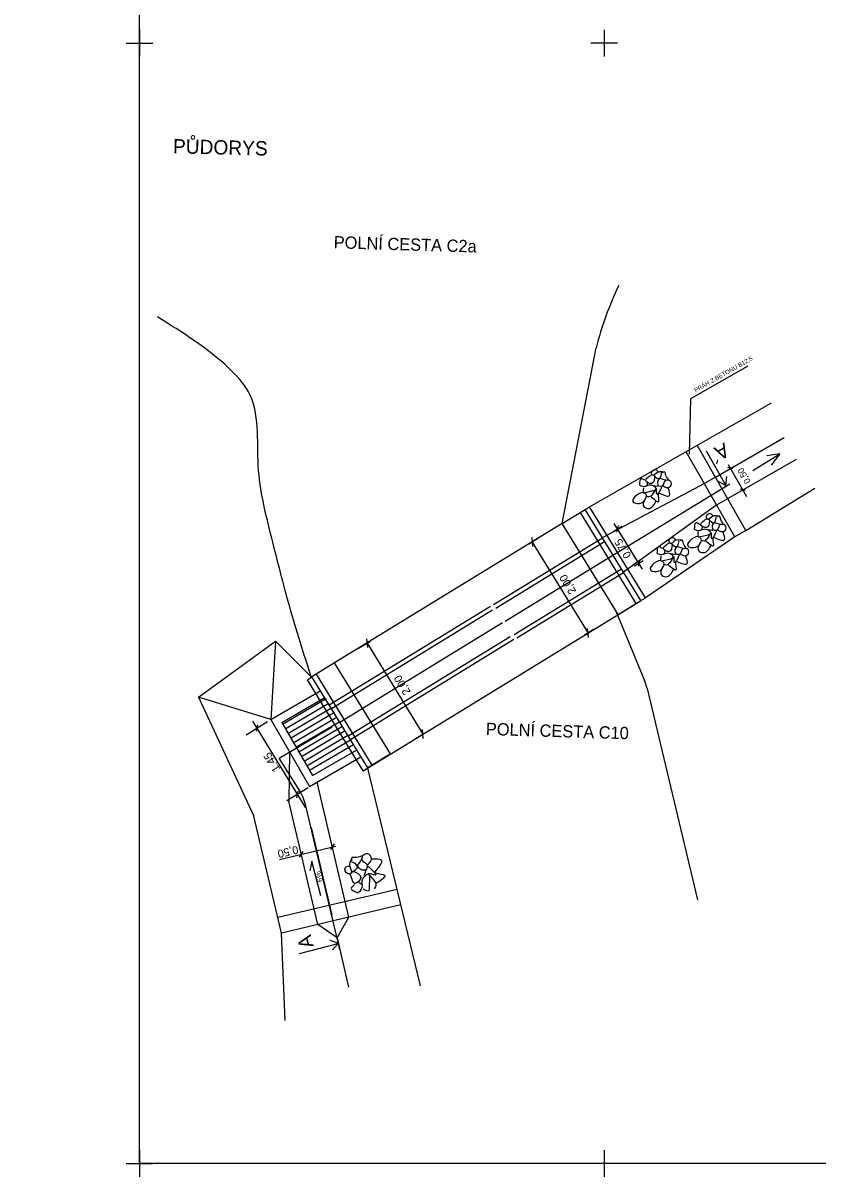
# Model space of a CAD drawing. Extents: x -463095.2 to -463031, y -1105061.3 to -1104976.3.
# Drawn here: x -463095.23 to -463065.46, y -1105061.31 to -1105018.06 of the extents above; entities that cross this region are included whole.
import ezdxf

# ---------------------------------------------------------------- set-up
doc = ezdxf.new("R2010")
doc.units = 0
for name, color, linetype in [('Implicitní', 7, 'Continuous'), ('Vrstva 14', 7, 'Continuous'), ('Vrstva 57', 7, 'Continuous')]:
    doc.layers.add(name, color=color, linetype=linetype)

msp = doc.modelspace()

# ---------------------------------------------------------------- linework, layer by layer
at = {"layer": 'Implicitní'}
for p, q in [((-463073.467, -1105018.311), (-463073.467, -1105019.311)), ((-463073.467, -1105018.311), (-463073.467, -1105019.311)), ((-463073.467, -1105018.311), (-463073.467, -1105019.311)), ((-463073.467, -1105018.311), (-463073.467, -1105019.311)), ((-463073.467, -1105018.312), (-463073.467, -1105019.312)), ((-463073.467, -1105018.312), (-463073.467, -1105019.312)), ((-463072.967, -1105018.811), (-463073.967, -1105018.811)), ((-463072.967, -1105018.811), (-463073.967, -1105018.811)), ((-463072.967, -1105018.811), (-463073.967, -1105018.811)), ((-463072.967, -1105018.811), (-463073.967, -1105018.811)), ((-463072.967, -1105018.812), (-463073.967, -1105018.812)), ((-463072.967, -1105018.812), (-463073.967, -1105018.812)), ((-463073.467, -1105060.311), (-463073.467, -1105061.311)), ((-463073.467, -1105060.311), (-463073.467, -1105061.311)), ((-463072.967, -1105060.811), (-463073.967, -1105060.811)), ((-463072.967, -1105060.811), (-463073.967, -1105060.811))]:
    msp.add_line(p, q, dxfattribs=at)
at = {"layer": 'Vrstva 14'}
for p, q in [((-463090.867, -1105018.311), (-463090.867, -1105019.311)), ((-463090.867, -1105018.311), (-463090.867, -1105019.311)), ((-463090.867, -1105018.312), (-463090.867, -1105019.312)), ((-463090.867, -1105018.312), (-463090.867, -1105019.312)), ((-463091.367, -1105018.811), (-463090.367, -1105018.811)), ((-463091.367, -1105018.811), (-463090.367, -1105018.811)), ((-463091.367, -1105018.812), (-463090.367, -1105018.812)), ((-463091.367, -1105018.812), (-463090.367, -1105018.812)), ((-463075.036, -1105036.821), (-463073.77, -1105030.236)), ((-463068.091, -1105030.92), (-463070.232, -1105032.146)), ((-463074.013, -1105036.194), (-463067.196, -1105032.29)), ((-463070.232, -1105032.146), (-463070.28, -1105034.219)), ((-463069.301, -1105035.076), (-463066.73, -1105033.595)), ((-463068.157, -1105037.081), (-463069.987, -1105033.888)), ((-463068.574, -1105037.32), (-463070.403, -1105034.127)), ((-463068.842, -1105035.886), (-463066.262, -1105034.412)), ((-463067.903, -1105034.83), (-463066.894, -1105034.206)), ((-463066.894, -1105034.206), (-463067.377, -1105034.28)), ((-463066.894, -1105034.206), (-463067.208, -1105034.63)), ((-463068.645, -1105034.771), (-463068.836, -1105034.718)), ((-463068.827, -1105034.607), (-463068.143, -1105035.801)), ((-463069.714, -1105035.315), (-463073.521, -1105037.347)), ((-463069.297, -1105035.077), (-463069.714, -1105035.315)), ((-463068.906, -1105035.389), (-463068.87, -1105035.054)), ((-463068.176, -1105035.579), (-463068.367, -1105035.526)), ((-463068.157, -1105037.081), (-463065.582, -1105035.499)), ((-463074.183, -1105036.299), (-463074.013, -1105036.194)), ((-463071.923, -1105039.605), (-463074.013, -1105036.194)), ((-463069.252, -1105036.123), (-463072.748, -1105038.647)), ((-463068.843, -1105035.889), (-463069.26, -1105036.127)), ((-463075.036, -1105036.821), (-463074.183, -1105036.299)), ((-463072.264, -1105039.814), (-463074.354, -1105036.403)), ((-463072.093, -1105039.709), (-463074.183, -1105036.299)), ((-463075.036, -1105036.821), (-463083.563, -1105042.046)), ((-463072.946, -1105040.232), (-463075.036, -1105036.821)), ((-463073.132, -1105037.117), (-463072.802, -1105036.913)), ((-463072.032, -1105038.532), (-463073.093, -1105036.815)), ((-463072.949, -1105036.895), (-463073.004, -1105037.137)), ((-463077.618, -1105039.858), (-463073.535, -1105037.356)), ((-463077.526, -1105039.989), (-463073.452, -1105037.492)), ((-463075.931, -1105037.37), (-463076.291, -1105037.59)), ((-463076.178, -1105037.345), (-463076.149, -1105037.679)), ((-463068.574, -1105037.32), (-463071.923, -1105039.605)), ((-463068.157, -1105037.081), (-463068.574, -1105037.32)), ((-463076.163, -1105037.512), (-463074.073, -1105040.923)), ((-463077.18, -1105040.481), (-463073.138, -1105038.004)), ((-463072.333, -1105038.41), (-463072.003, -1105038.206)), ((-463072.14, -1105038.178), (-463072.196, -1105038.419)), ((-463076.836, -1105040.973), (-463072.825, -1105038.516)), ((-463076.744, -1105041.105), (-463072.741, -1105038.652)), ((-463072.093, -1105039.709), (-463071.923, -1105039.605)), ((-463077.731, -1105039.927), (-463083.767, -1105043.626)), ((-463077.647, -1105040.063), (-463083.684, -1105043.762)), ((-463082.496, -1105046.084), (-463072.085, -1105039.704)), ((-463072.946, -1105040.232), (-463072.093, -1105039.709)), ((-463073.024, -1105040.124), (-463071.957, -1105042.697)), ((-463077.274, -1105040.538), (-463083.37, -1105044.274)), ((-463073.841, -1105040.78), (-463074.201, -1105041.001)), ((-463074.059, -1105041.09), (-463074.088, -1105040.755)), ((-463088.659, -1105043.332), (-463085.777, -1105041.23)), ((-463085.777, -1105041.23), (-463085.957, -1105044.169)), ((-463084.438, -1105042.57), (-463085.777, -1105041.23)), ((-463076.989, -1105041.067), (-463083.057, -1105044.785)), ((-463076.846, -1105041.167), (-463082.973, -1105044.922)), ((-463082.667, -1105041.497), (-463082.222, -1105041.224)), ((-463082.365, -1105041.136), (-463082.336, -1105041.47)), ((-463082.35, -1105041.303), (-463080.26, -1105044.714)), ((-463083.563, -1105042.046), (-463084.415, -1105042.568)), ((-463081.473, -1105045.456), (-463083.563, -1105042.046)), ((-463084.586, -1105042.673), (-463084.415, -1105042.568)), ((-463082.496, -1105046.083), (-463084.586, -1105042.673)), ((-463082.325, -1105045.979), (-463084.415, -1105042.568)), ((-463082.155, -1105045.874), (-463084.245, -1105042.464)), ((-463085.957, -1105044.169), (-463084.085, -1105043.084)), ((-463071.859, -1105042.999), (-463069.969, -1105050.921)), ((-463088.659, -1105043.332), (-463086.589, -1105047.788)), ((-463085.957, -1105044.169), (-463088.659, -1105043.332)), ((-463085.547, -1105044.278), (-463083.952, -1105043.353)), ((-463083.878, -1105043.39), (-463085.519, -1105044.357)), ((-463083.777, -1105043.563), (-463085.417, -1105044.529)), ((-463083.675, -1105043.735), (-463085.316, -1105044.702)), ((-463083.574, -1105043.907), (-463085.214, -1105044.874)), ((-463086.074, -1105044.258), (-463086.873, -1105044.747)), ((-463086.642, -1105044.23), (-463084.653, -1105047.477)), ((-463086.496, -1105044.607), (-463086.439, -1105044.366)), ((-463085.957, -1105044.169), (-463084.502, -1105046.678)), ((-463085.547, -1105044.278), (-463084.393, -1105046.268)), ((-463083.472, -1105044.08), (-463085.113, -1105045.046)), ((-463083.371, -1105044.252), (-463085.011, -1105045.219)), ((-463095.232, -1105044.423), (-463095.232, -1105044.423)), ((-463094.581, -1105044.423), (-463094.581, -1105044.423)), ((-463083.269, -1105044.424), (-463084.91, -1105045.391)), ((-463083.167, -1105044.596), (-463084.808, -1105045.563)), ((-463083.066, -1105044.769), (-463084.706, -1105045.736)), ((-463080.577, -1105044.908), (-463080.132, -1105044.635)), ((-463080.246, -1105044.881), (-463080.275, -1105044.546)), ((-463082.964, -1105044.941), (-463084.605, -1105045.908)), ((-463082.863, -1105045.113), (-463084.503, -1105046.08)), ((-463084.502, -1105046.678), (-463082.587, -1105045.567)), ((-463084.393, -1105046.268), (-463082.745, -1105045.312)), ((-463081.473, -1105045.456), (-463082.325, -1105045.979)), ((-463082.496, -1105046.083), (-463082.325, -1105045.979)), ((-463082.329, -1105045.983), (-463080.355, -1105054.151)), ((-463084.559, -1105046.73), (-463085.357, -1105047.219)), ((-463084.985, -1105047.096), (-463084.928, -1105046.855)), ((-463083.367, -1105052.789), (-463084.644, -1105047.396)), ((-463083.661, -1105051.504), (-463084.435, -1105048.208)), ((-463085.623, -1105049.407), (-463083.516, -1105048.912)), ((-463084.759, -1105049.112), (-463084.89, -1105049.322)), ((-463083.582, -1105048.829), (-463083.714, -1105049.039)), ((-463081.218, -1105050.531), (-463085.696, -1105051.584)), ((-463081.081, -1105051.117), (-463085.559, -1105052.17)), ((-463083.43, -1105052.56), (-463083.744, -1105052.437)), ((-463083.47, -1105052.349), (-463083.043, -1105054.2)), ((-463090.867, -1105060.311), (-463090.867, -1105061.311)), ((-463091.367, -1105060.811), (-463090.367, -1105060.811))]:
    msp.add_line(p, q, dxfattribs=at)
msp.add_lwpolyline([(-463090.867, -1105060.811), (-463090.867, -1104976.812), (-463031.467, -1104976.812), (-463031.467, -1105060.811)], close=True, dxfattribs=at)
for points in [[(-463069.649, -1105034.092), (-463068.906, -1105035.389), (-463069.199, -1105035.243)], [(-463073.59, -1105038.283), (-463068.761, -1105035.331)], [(-463084.894, -1105046.797), (-463085.635, -1105045.611), (-463083.657, -1105044.446)], [(-463085.262, -1105045.375), (-463085.259, -1105045.378), (-463085.284, -1105047.221)], [(-463083.47, -1105052.349), (-463083.027, -1105051.576), (-463084.218, -1105046.512)], [(-463083.47, -1105052.349), (-463084.195, -1105051.845), (-463085.284, -1105047.221)], [(-463085.419, -1105055.452), (-463085.559, -1105052.17), (-463086.589, -1105047.788)], [(-463084.075, -1105050.775), (-463084.415, -1105049.469), (-463084.487, -1105049.843)], [(-463084.877, -1105052.935), (-463083.43, -1105052.56), (-463083.648, -1105052.804)]]:
    msp.add_lwpolyline(points, dxfattribs=at)
for centre, radius, start, end in [((-463061.322, -1105033.416), 12.848, 154.5646, 165.6667), ((-463073.805, -1105043.463), 2, 13.4219, 22.5132), ((-463086.59, -1105047.857), 2, 13.3222, 31.992)]:
    msp.add_arc(centre, radius, start, end, dxfattribs=at)
for points in [[(-463084.438, -1105042.57), (-463085.247, -1105039.939), (-463085.919, -1105037.363), (-463086.422, -1105034.659), (-463086.79, -1105031.879), (-463087.515, -1105031.004), (-463090.196, -1105029.076)], [(-463071.237, -1105034.893), (-463071.47, -1105034.907), (-463071.65, -1105035.01), (-463071.693, -1105034.915), (-463071.536, -1105034.791), (-463071.458, -1105034.889)], [(-463071.389, -1105035.122), (-463071.064, -1105035.176), (-463071.154, -1105035.021), (-463071.208, -1105034.887), (-463071.291, -1105034.913)], [(-463071.943, -1105035.2), (-463072.086, -1105035.14), (-463072.149, -1105035.371)], [(-463071.857, -1105035.293), (-463071.88, -1105035.404), (-463072.078, -1105035.419), (-463072.144, -1105035.38)], [(-463071.579, -1105035.056), (-463071.691, -1105035.318), (-463071.909, -1105035.202), (-463071.778, -1105035.05), (-463071.676, -1105034.981)], [(-463071.625, -1105034.996), (-463071.405, -1105035.132), (-463071.326, -1105034.967), (-463071.325, -1105034.911)], [(-463071.602, -1105035.397), (-463071.441, -1105035.392), (-463071.464, -1105035.296), (-463071.401, -1105035.14)], [(-463071.469, -1105035.393), (-463071.267, -1105035.392), (-463071.234, -1105035.318), (-463071.153, -1105035.173)], [(-463071.277, -1105035.392), (-463071.102, -1105035.471), (-463070.96, -1105035.378), (-463070.965, -1105035.272), (-463071.073, -1105035.177)], [(-463071.876, -1105035.772), (-463071.952, -1105035.671), (-463072.394, -1105035.997), (-463071.996, -1105036.003), (-463071.913, -1105035.865)], [(-463071.999, -1105035.483), (-463071.992, -1105035.665), (-463071.854, -1105035.639), (-463071.527, -1105035.508), (-463071.696, -1105035.384), (-463071.884, -1105035.417)], [(-463071.289, -1105035.393), (-463071.499, -1105035.709), (-463071.509, -1105035.519), (-463071.755, -1105035.811), (-463071.904, -1105035.799)], [(-463071.709, -1105035.818), (-463071.422, -1105035.993), (-463071.439, -1105035.719), (-463071.43, -1105035.658)], [(-463071.406, -1105035.683), (-463071.017, -1105035.767), (-463071.069, -1105035.49)], [(-463071.894, -1105035.836), (-463071.985, -1105036.177), (-463071.813, -1105036.258), (-463071.516, -1105035.962)], [(-463069.526, -1105036.71), (-463069.638, -1105036.971), (-463069.855, -1105036.856), (-463069.724, -1105036.704), (-463069.622, -1105036.634)], [(-463069.184, -1105036.547), (-463069.416, -1105036.56), (-463069.596, -1105036.664), (-463069.64, -1105036.569), (-463069.482, -1105036.445), (-463069.404, -1105036.542)], [(-463069.571, -1105036.649), (-463069.351, -1105036.785), (-463069.273, -1105036.62), (-463069.272, -1105036.564)], [(-463069.335, -1105036.776), (-463069.011, -1105036.83), (-463069.1, -1105036.674), (-463069.154, -1105036.541), (-463069.237, -1105036.567)], [(-463069.889, -1105036.854), (-463070.033, -1105036.794), (-463070.095, -1105037.025)], [(-463069.803, -1105036.946), (-463069.826, -1105037.057), (-463070.024, -1105037.073), (-463070.091, -1105037.033)], [(-463069.945, -1105037.136), (-463069.938, -1105037.319), (-463069.8, -1105037.293), (-463069.474, -1105037.161), (-463069.642, -1105037.038), (-463069.83, -1105037.07)], [(-463069.235, -1105037.047), (-463069.445, -1105037.362), (-463069.456, -1105037.173), (-463069.701, -1105037.465), (-463069.851, -1105037.453)], [(-463069.548, -1105037.051), (-463069.387, -1105037.045), (-463069.41, -1105036.95), (-463069.347, -1105036.794)], [(-463069.416, -1105037.047), (-463069.213, -1105037.045), (-463069.18, -1105036.971), (-463069.099, -1105036.827)], [(-463069.223, -1105037.045), (-463069.048, -1105037.124), (-463068.906, -1105037.032), (-463068.911, -1105036.926), (-463069.019, -1105036.831)], [(-463070.581, -1105037.448), (-463070.813, -1105037.461), (-463070.994, -1105037.564), (-463071.037, -1105037.469), (-463070.879, -1105037.346), (-463070.801, -1105037.443)], [(-463070.969, -1105037.55), (-463070.749, -1105037.686), (-463070.67, -1105037.521), (-463070.669, -1105037.465)], [(-463070.732, -1105037.676), (-463070.408, -1105037.73), (-463070.497, -1105037.575), (-463070.551, -1105037.442), (-463070.634, -1105037.467)], [(-463069.822, -1105037.425), (-463069.898, -1105037.325), (-463070.34, -1105037.65), (-463069.942, -1105037.656), (-463069.859, -1105037.518)], [(-463069.841, -1105037.489), (-463069.931, -1105037.831), (-463069.759, -1105037.911), (-463069.462, -1105037.616)], [(-463069.655, -1105037.472), (-463069.369, -1105037.647), (-463069.386, -1105037.373), (-463069.376, -1105037.312)], [(-463069.353, -1105037.337), (-463068.964, -1105037.421), (-463069.015, -1105037.144)], [(-463071.287, -1105037.754), (-463071.43, -1105037.694), (-463071.493, -1105037.926)], [(-463071.201, -1105037.847), (-463071.224, -1105037.958), (-463071.421, -1105037.973), (-463071.488, -1105037.934)], [(-463071.343, -1105038.037), (-463071.336, -1105038.219), (-463071.198, -1105038.194), (-463070.871, -1105038.062), (-463071.039, -1105037.939), (-463071.227, -1105037.971)], [(-463070.923, -1105037.61), (-463071.035, -1105037.872), (-463071.252, -1105037.757), (-463071.122, -1105037.605), (-463071.02, -1105037.535)], [(-463070.945, -1105037.951), (-463070.784, -1105037.946), (-463070.808, -1105037.85), (-463070.744, -1105037.694)], [(-463070.813, -1105037.948), (-463070.611, -1105037.946), (-463070.578, -1105037.872), (-463070.496, -1105037.728)], [(-463070.62, -1105037.946), (-463070.446, -1105038.025), (-463070.304, -1105037.932), (-463070.309, -1105037.827), (-463070.417, -1105037.732)], [(-463071.219, -1105038.326), (-463071.295, -1105038.226), (-463071.738, -1105038.551), (-463071.34, -1105038.557), (-463071.256, -1105038.419)], [(-463070.632, -1105037.947), (-463070.842, -1105038.263), (-463070.853, -1105038.074), (-463071.099, -1105038.366), (-463071.248, -1105038.353)], [(-463071.053, -1105038.372), (-463070.766, -1105038.548), (-463070.783, -1105038.273), (-463070.774, -1105038.213)], [(-463070.75, -1105038.238), (-463070.361, -1105038.321), (-463070.413, -1105038.045)], [(-463071.238, -1105038.39), (-463071.328, -1105038.731), (-463071.157, -1105038.812), (-463070.86, -1105038.516)], [(-463082.932, -1105049.393), (-463082.999, -1105049.676), (-463082.94, -1105049.929), (-463083.069, -1105049.947), (-463083.161, -1105049.714), (-463083.016, -1105049.656)], [(-463082.948, -1105049.894), (-463082.707, -1105049.679), (-463082.876, -1105049.526), (-463082.943, -1105049.505)], [(-463082.712, -1105049.656), (-463082.532, -1105049.287), (-463082.75, -1105049.338), (-463082.929, -1105049.356), (-463082.928, -1105049.464)], [(-463082.416, -1105049.849), (-463082.346, -1105049.607), (-463082.423, -1105049.541), (-463082.567, -1105049.392)], [(-463082.349, -1105049.618), (-463082.193, -1105049.437), (-463082.253, -1105049.234), (-463082.381, -1105049.202), (-463082.534, -1105049.298)], [(-463082.046, -1105049.877), (-463081.807, -1105049.441), (-463082.157, -1105049.404)], [(-463082.859, -1105049.861), (-463082.586, -1105050.089), (-463082.802, -1105050.308), (-463082.937, -1105050.097), (-463082.984, -1105049.95)], [(-463082.459, -1105050.009), (-463082.408, -1105049.815), (-463082.531, -1105049.808), (-463082.695, -1105049.677)], [(-463082.498, -1105050.516), (-463082.277, -1105050.573), (-463082.258, -1105050.398), (-463082.3, -1105049.96), (-463082.507, -1105050.117), (-463082.536, -1105050.354)], [(-463082.352, -1105049.633), (-463082.049, -1105049.997), (-463082.279, -1105049.942), (-463082.017, -1105050.341), (-463082.085, -1105050.515)], [(-463081.993, -1105050.288), (-463081.681, -1105050.007), (-463082.015, -1105049.93), (-463082.085, -1105049.897)], [(-463082.817, -1105050.348), (-463082.94, -1105050.498), (-463082.685, -1105050.656)], [(-463082.675, -1105050.278), (-463082.55, -1105050.345), (-463082.602, -1105050.587), (-463082.673, -1105050.653)]]:
    msp.add_spline(points, degree=3, dxfattribs=at)

# ---------------------------------------------------------------- texts
for s, height, rotation, p in [('PŮDORYS', 0.536, 358.5898, (-463089.622, -1105022.942)), ('A´', 0.536, 207.7449, (-463068.967, -1105033.774)), ('0,50', 0.24, 119.8041, (-463067.973, -1105035.246)), ('0,75', 0.3, 121.7127, (-463072.439, -1105038.014)), ('2,00', 0.3, 121.4976, (-463074.505, -1105039.357)), ('2,00', 0.3, 121.4976, (-463080.702, -1105043.131)), ('1,45', 0.3, 121.4976, (-463085.586, -1105046.022)), ('0,50', 0.3, 193.229, (-463084.963, -1105048.892)), ('A', 0.536, 104.5585, (-463084.338, -1105052.665))]:
    msp.add_text(s, height=height, rotation=rotation, dxfattribs=at).set_placement(p)
at = {"layer": 'Vrstva 57'}
for s, height, rotation, p in [('POLNÍ CESTA C2a', 0.459, 358.2755, (-463083.603, -1105026.501)), ('PRÁH Z BETONU B12,5', 0.1632, 29.8041, (-463070.039, -1105031.91)), ('POLNÍ CESTA C10', 0.459, 358.2755, (-463077.905, -1105044.744)), ('6%', 0.204, 104.5585, (-463084.004, -1105050.23))]:
    msp.add_text(s, height=height, rotation=rotation, dxfattribs=at).set_placement(p)

doc.saveas('drawing.dxf')
